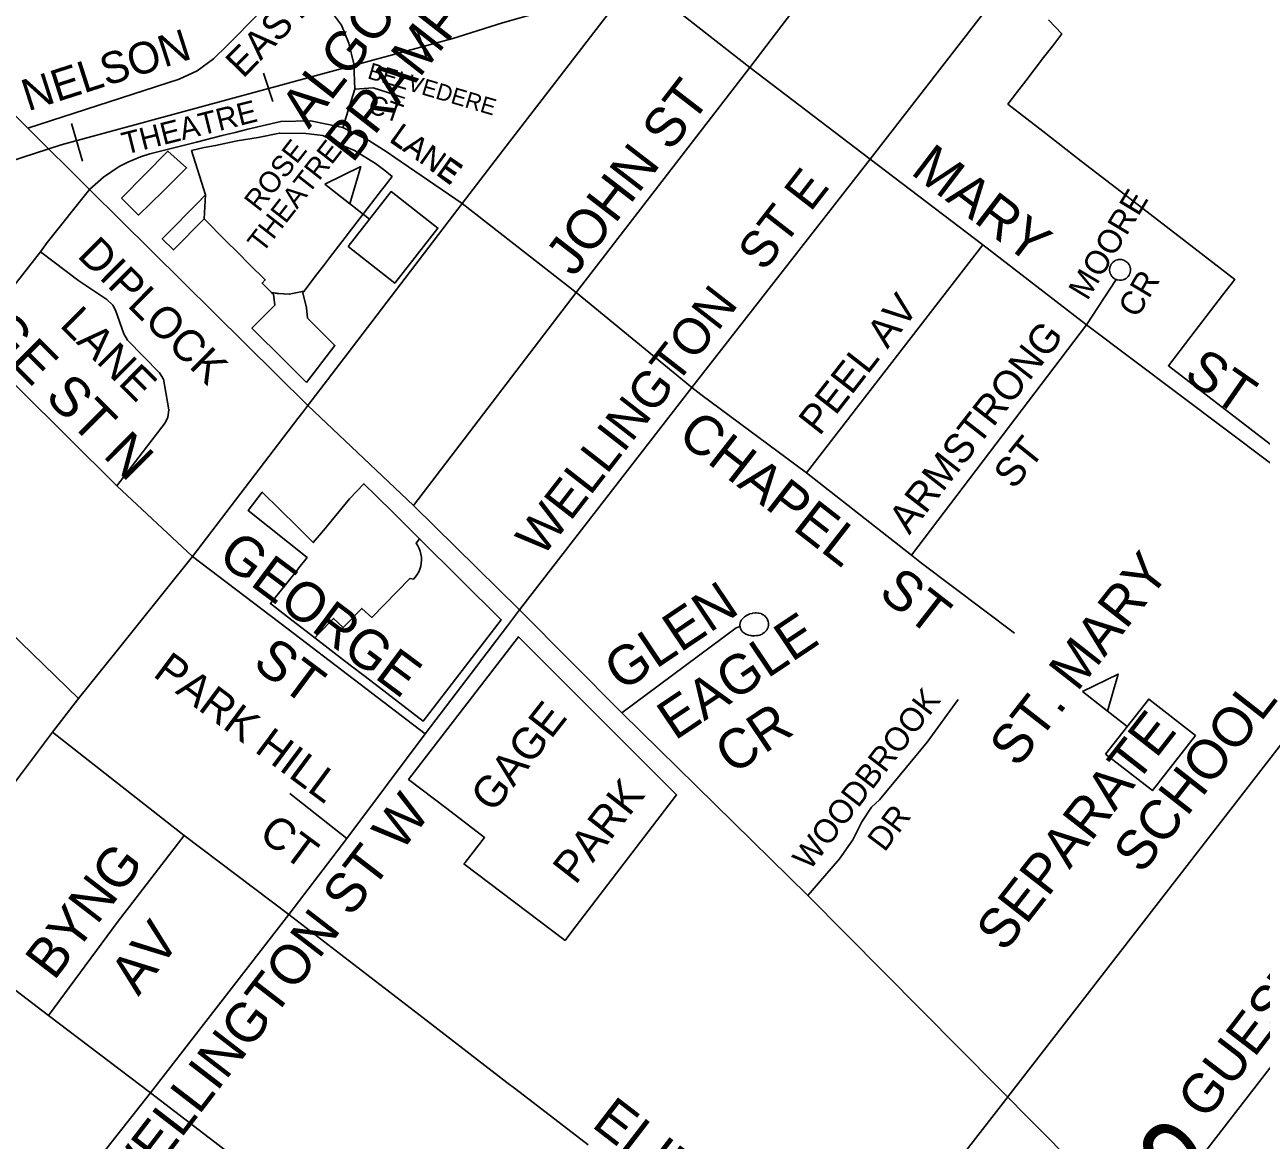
# Model space of a CAD drawing. Extents: x 586326 to 623965, y 4819854 to 4857850.
# Drawn here: x 599765 to 600548, y 4837268 to 4837975 of the extents above; entities that cross this region are included whole.
import ezdxf

# ---------------------------------------------------------------- set-up
doc = ezdxf.new("R2010")
doc.units = 0
for name, color, linetype in [('Lots_Concessions', 7, 'Continuous'), ('Major Rds and Hwys', 7, 'Continuous'), ('Major Rds Lbls', 7, 'Continuous'), ('Minor Rd Lbls', 7, 'Continuous'), ('Minor Rds', 7, 'Continuous'), ('Park Lbls', 7, 'Continuous'), ('Park Outlines', 7, 'Continuous'), ('Private Rd Lbls', 7, 'Continuous'), ('Private Rds', 7, 'Continuous'), ('Proposed Secondary Rds', 7, 'Continuous'), ('Pts of Interest', 7, 'Continuous'), ('Railways_lbls', 7, 'Continuous'), ('School Syms_Lbls', 7, 'Continuous'), ('Secondary Rds Lbls', 7, 'Continuous')]:
    doc.layers.add(name, color=color, linetype=linetype)

msp = doc.modelspace()

# ---------------------------------------------------------------- linework, layer by layer
at = {"layer": 'Lots_Concessions'}
for p, q in [((600387.79, 4837295.98), (600638.9, 4837619.9)), ((600308.22, 4837193.39), (600387.96, 4837296.17))]:
    msp.add_line(p, q, dxfattribs=at)
at = {"layer": 'Major Rds and Hwys'}
for points in [[(600069.85, 4837898.16), (600151.75, 4838004.72)], [(599766.6, 4837909.61), (599693.66, 4837982.93)], [(599805.77, 4837870.74), (599766.6, 4837909.61)], [(600042.05, 4837861.99), (600069.85, 4837898.16)], [(599944.17, 4837733.92), (599805.77, 4837870.74)], [(599944.17, 4837733.92), (599966.9, 4837763.68), (600042.05, 4837861.99)], [(599944.17, 4837733.92), (599941.01, 4837729.79), (599937.86, 4837725.67), (599871.13, 4837638.37)], [(599944.17, 4837733.92), (600011.24, 4837670.53)], [(600011.24, 4837670.53), (600078.31, 4837604.38)], [(599871.13, 4837638.37), (599835.07, 4837593.4), (599820.8, 4837575.6), (599818.11, 4837572.24), (599798.91, 4837548.29)], [(600078.31, 4837604.38), (600143.08, 4837539.15)], [(599798.91, 4837548.29), (599782.24, 4837526.96)], [(600143.08, 4837539.15), (600261.14, 4837423.38)], [(599782.24, 4837526.96), (599727.66, 4837454.38)], [(600261.14, 4837423.38), (600453.75, 4837229.28)]]:
    msp.add_lwpolyline(points, dxfattribs=at)
at = {"layer": 'Minor Rds'}
for points in [[(599766.6, 4837909.61), (599862.72, 4837940.59), (599873.96, 4837945.89), (599884.48, 4837953.64), (599893.1, 4837961.93), (599933.45, 4838002.96)], [(599933.45, 4838002.96), (599942.46, 4837997.39), (599948.24, 4837993.47), (599953.94, 4837988.08), (599959.77, 4837982.59), (599965.59, 4837974.93), (599970.08, 4837963.45), (599973.41, 4837950.48), (599973.91, 4837934.34)], [(600300.61, 4837889.91), (600378.98, 4837991.06), (600381.64, 4837994.46), (600383.31, 4837997.87)], [(600161.59, 4837982.44), (600169.54, 4837986.3), (600172.9, 4837986.96), (600176.85, 4837985.33), (600224.28, 4837948.01)], [(600114.14, 4837805.59), (600224.28, 4837948.01)], [(599973.91, 4837934.34), (599966.25, 4837910.05)], [(599873.65, 4837900.85), (599889.92, 4837904.95), (599898.06, 4837907), (599906.19, 4837909.05), (599926.99, 4837913.87), (599945.96, 4837914.37), (599956.11, 4837912.21), (599966.25, 4837910.05)], [(599966.25, 4837910.05), (599982.73, 4837901.73), (599994.37, 4837894.41), (599999.41, 4837890.98), (600042.05, 4837861.99)], [(599805.77, 4837870.74), (599814.62, 4837878.59), (599824.61, 4837885.33), (599830.03, 4837888.04), (599838.1, 4837891.49), (599844.12, 4837893.4), (599873.65, 4837900.85)], [(600300.61, 4837889.91), (600371.9, 4837835.63)], [(599805.77, 4837870.74), (599778.96, 4837837.28), (599774.72, 4837831.34)], [(600042.05, 4837861.99), (600114.14, 4837805.59)], [(600260.22, 4837691.2), (600371.9, 4837835.63)], [(600371.9, 4837835.63), (600437.76, 4837785.07)], [(599774.72, 4837831.34), (599730.31, 4837774.94)], [(599774.72, 4837831.34), (599799.02, 4837813.02), (599816.81, 4837801.09), (599820.59, 4837797.59), (599822.28, 4837794.35), (599827.63, 4837779.43), (599829.79, 4837775.43), (599850.23, 4837754.68), (599852.76, 4837750.72), (599856.09, 4837731.11), (599855.51, 4837726.57), (599853.66, 4837722.93), (599823.05, 4837682.97)], [(600456.43, 4837813.76), (600455.52, 4837814.22), (600455.31, 4837814.34), (600455.11, 4837814.47), (600454.92, 4837814.62), (600454.26, 4837815.2), (600454.08, 4837815.36), (600453.92, 4837815.54), (600453.77, 4837815.73), (600453.26, 4837816.45), (600453.13, 4837816.65), (600453.02, 4837816.86), (600452.92, 4837817.08), (600452.6, 4837817.9), (600452.52, 4837818.13), (600452.46, 4837818.36), (600452.42, 4837818.6), (600452.3, 4837819.47), (600452.28, 4837819.71), (600452.27, 4837819.95), (600452.29, 4837820.19), (600452.38, 4837821.06), (600452.42, 4837821.29), (600452.47, 4837821.52), (600452.53, 4837821.74), (600452.62, 4837821.95), (600453.04, 4837822.9), (600453.13, 4837823.08), (600453.23, 4837823.26), (600453.34, 4837823.44), (600453.47, 4837823.6), (600454.13, 4837824.39), (600454.27, 4837824.55), (600454.41, 4837824.69), (600454.57, 4837824.83), (600454.74, 4837824.95), (600455.59, 4837825.54), (600455.76, 4837825.65), (600455.94, 4837825.75), (600456.13, 4837825.83), (600456.32, 4837825.91), (600457.3, 4837826.24), (600457.5, 4837826.3), (600457.7, 4837826.35), (600457.9, 4837826.38), (600458.11, 4837826.4), (600459.14, 4837826.45), (600459.4, 4837826.45), (600459.65, 4837826.43), (600459.91, 4837826.39), (600461.41, 4837825.92)], [(600461.41, 4837825.92), (600461.93, 4837825.69), (600462.66, 4837825.27), (600462.86, 4837825.14), (600463.05, 4837824.99), (600463.23, 4837824.84), (600463.84, 4837824.26), (600464, 4837824.08), (600464.16, 4837823.9), (600464.29, 4837823.7), (600464.75, 4837822.99), (600464.87, 4837822.79), (600464.97, 4837822.57), (600465.06, 4837822.35), (600465.33, 4837821.55), (600465.4, 4837821.33), (600465.45, 4837821.09), (600465.48, 4837820.86), (600465.56, 4837820.02), (600465.57, 4837819.78), (600465.56, 4837819.54), (600465.54, 4837819.3), (600465.41, 4837818.47), (600465.37, 4837818.24), (600465.31, 4837818.01), (600465.23, 4837817.78), (600464.91, 4837817), (600464.81, 4837816.78), (600464.7, 4837816.58), (600464.56, 4837816.38), (600464.07, 4837815.69), (600463.93, 4837815.51), (600463.76, 4837815.33), (600463.59, 4837815.17), (600462.95, 4837814.62), (600462.76, 4837814.47), (600462.56, 4837814.34), (600462.36, 4837814.22), (600461.6, 4837813.84), (600461.41, 4837813.75), (600461.2, 4837813.67), (600460.99, 4837813.61), (600460.14, 4837813.39), (600459.91, 4837813.34), (600459.67, 4837813.31), (600459.43, 4837813.3), (600458.55, 4837813.29), (600457.12, 4837813.45), (600456.43, 4837813.76)], [(600437.76, 4837785.07), (600456.43, 4837813.76)], [(600011.24, 4837670.53), (600114.14, 4837805.59)], [(600114.14, 4837805.59), (600187.64, 4837745.41)], [(600326.78, 4837639.03), (600437.76, 4837785.07)], [(600437.76, 4837785.07), (600612.99, 4837653.35)], [(599823.05, 4837682.97), (599730.31, 4837774.94)], [(600187.64, 4837745.41), (600193.16, 4837740.89), (600260.22, 4837691.2)], [(600260.22, 4837691.2), (600326.78, 4837639.03)], [(599798.91, 4837548.29), (599659.24, 4837683.67)], [(599871.13, 4837638.37), (599823.05, 4837682.97)], [(599871.13, 4837638.37), (599931.69, 4837592.14), (600018.59, 4837525.82)], [(600326.78, 4837639.03), (600333.04, 4837634.06), (600392.12, 4837589.69)], [(600218.09, 4837593.88), (600218.01, 4837594.36), (600217.98, 4837594.79), (600217.99, 4837595.01), (600218.02, 4837595.23), (600218.16, 4837596.11), (600218.2, 4837596.32), (600218.25, 4837596.53), (600218.33, 4837596.74), (600218.41, 4837596.93), (600218.79, 4837597.74), (600218.89, 4837597.93), (600219.01, 4837598.11), (600219.13, 4837598.29), (600219.27, 4837598.45), (600219.42, 4837598.61), (600220.49, 4837599.64), (600220.68, 4837599.81), (600220.88, 4837599.96), (600222.11, 4837600.8), (600222.32, 4837600.94), (600222.54, 4837601.05), (600223.89, 4837601.68), (600224.12, 4837601.77), (600224.36, 4837601.85), (600225.8, 4837602.24), (600226.04, 4837602.3), (600226.29, 4837602.34), (600227.77, 4837602.49), (600228.02, 4837602.5), (600228.27, 4837602.5), (600229.76, 4837602.4), (600230.01, 4837602.37), (600230.26, 4837602.32), (600231.25, 4837602.09), (600231.49, 4837602.02), (600231.73, 4837601.93), (600231.96, 4837601.82), (600232.86, 4837601.34), (600233.08, 4837601.21), (600233.28, 4837601.07), (600233.48, 4837600.9), (600234.23, 4837600.22), (600234.41, 4837600.04), (600234.57, 4837599.84), (600234.72, 4837599.64), (600235.27, 4837598.78), (600235.4, 4837598.57), (600235.51, 4837598.34), (600235.6, 4837598.1), (600235.92, 4837597.14), (600235.99, 4837596.89), (600236.04, 4837596.64), (600236.07, 4837596.39), (600236.14, 4837595.38), (600236.14, 4837595.12), (600236.13, 4837594.87), (600236.09, 4837594.62), (600235.91, 4837593.62), (600235.85, 4837593.36), (600235.76, 4837593.12), (600235.66, 4837592.87), (600235.54, 4837592.64), (600234.98, 4837591.71), (600234.88, 4837591.54), (600234.75, 4837591.38), (600234.62, 4837591.22), (600233.89, 4837590.42), (600233.75, 4837590.28), (600233.6, 4837590.14), (600233.44, 4837590.02), (600232.57, 4837589.38), (600232.4, 4837589.27), (600232.22, 4837589.16), (600232.04, 4837589.07), (600231.05, 4837588.63), (600230.87, 4837588.55), (600230.67, 4837588.48), (600230.48, 4837588.43), (600229.42, 4837588.19), (600229.17, 4837588.15), (600228.92, 4837588.12), (600228.66, 4837588.12), (600228.45, 4837588.13), (600227.23, 4837588.01), (600226.75, 4837588)], [(600143.08, 4837539.15), (600215.54, 4837593.01), (600218.09, 4837593.88)], [(600226.75, 4837588), (600225.33, 4837588.09), (600225.09, 4837588.11), (600224.86, 4837588.16), (600223.47, 4837588.47), (600223.24, 4837588.53), (600223.02, 4837588.61), (600221.69, 4837589.14), (600221.52, 4837589.21), (600221.36, 4837589.3), (600221.2, 4837589.39), (600220.45, 4837589.87), (600220.27, 4837589.99), (600220.1, 4837590.13), (600219.94, 4837590.27), (600219.79, 4837590.43), (600219.21, 4837591.11), (600219.07, 4837591.27), (600218.95, 4837591.45), (600218.84, 4837591.64), (600218.74, 4837591.83), (600218.36, 4837592.72), (600218.09, 4837593.88)], [(599782.24, 4837526.96), (599865.7, 4837461.44)], [(599932.78, 4837488.02), (599968.97, 4837459.67)], [(599865.7, 4837461.44), (599823.3, 4837406.37), (599779.82, 4837347.46)], [(599865.7, 4837461.44), (599932.22, 4837411.44)], [(600473.51, 4837210.46), (600639.8, 4837425.2)], [(599694.77, 4837412.28), (599779.82, 4837347.46)], [(599932.22, 4837411.44), (600017.2, 4837345.93), (600070.26, 4837305.02), (600075.9, 4837300.86), (600121.87, 4837265.5)], [(599779.82, 4837347.46), (599844.48, 4837298.43)], [(599844.48, 4837298.43), (600036.69, 4837150.98)]]:
    msp.add_lwpolyline(points, dxfattribs=at)
at = {"layer": 'Park Outlines'}
msp.add_lwpolyline([(600413.62, 4837978.23), (600422.08, 4837969.31), (600416.3, 4837961.81), (600410.53, 4837954.31), (600399.19, 4837939.59), (600393.39, 4837932.07), (600387.86, 4837924.88), (600399.87, 4837915.51), (600409.98, 4837907.67), (600434.38, 4837888.78), (600459.63, 4837869.33), (600465.18, 4837865.06), (600500.98, 4837837.48), (600531.69, 4837813.83), (600523.95, 4837803.78), (600503.85, 4837777.66), (600489.56, 4837759.1), (600579.88, 4837689.6)], dxfattribs=at)
for points in [[(599942.85, 4837906.27), (599926.18, 4837906.56), (599912.63, 4837903.76), (599899.43, 4837901.54), (599885.71, 4837898.66), (599878.54, 4837897.33), (599870.45, 4837895.39), (599879.29, 4837867.36), (599878.39, 4837852.12), (599892.25, 4837838.33), (599899.77, 4837830.84), (599907.06, 4837823.58), (599917.21, 4837813.49), (599915.18, 4837811.48), (599921.23, 4837805.43), (599925.72, 4837804.85), (599932.35, 4837804.4), (599940.74, 4837806.24), (599941.64, 4837806.15), (599950.12, 4837817.27), (599954.01, 4837822.35), (599957.91, 4837827.42), (599965.7, 4837837.57), (599977.6, 4837853.06), (599990.96, 4837870.45), (599992.46, 4837872.41), (599997.52, 4837878.93), (599993.05, 4837882.73), (599986.95, 4837887.19), (599973.83, 4837895.4), (599965.61, 4837898.89), (599953.63, 4837905.05)], [(599826.16, 4837865.23), (599829.11, 4837862.29), (599836.9, 4837854.53), (599852.37, 4837869.72), (599867.35, 4837884.43), (599861.35, 4837889.75), (599855.35, 4837895.07)], [(599879.29, 4837867.36), (599876.8, 4837864.84), (599876.72, 4837864.76), (599851.93, 4837839.56), (599859.05, 4837832.47), (599878.39, 4837852.12)], [(599943.35, 4837748.48), (599958.6, 4837768.33), (599961.36, 4837771.91), (599943.96, 4837789.26), (599943.25, 4837795.84), (599940.74, 4837806.24), (599932.35, 4837804.4), (599928.73, 4837804.64), (599925.72, 4837804.85), (599924.69, 4837804.93), (599921.23, 4837805.43), (599922.4, 4837804.46), (599923.16, 4837797.43), (599908.71, 4837782.99), (599910.87, 4837780.84), (599916.33, 4837775.41), (599922.17, 4837769.59), (599925.18, 4837766.58), (599936.97, 4837754.85)], [(599948.6, 4837586.73), (599950.62, 4837589.05), (599960.47, 4837599.07), (599966.56, 4837593.29), (599978.38, 4837605.36), (599984.74, 4837599.67), (600008.87, 4837624.36), (600011.11, 4837623.9), (600012.38, 4837625.32), (600013.49, 4837626.87), (600014.42, 4837628.54), (600015.17, 4837630.3), (600015.72, 4837632.13), (600016.06, 4837634), (600016.2, 4837635.91), (600016.12, 4837637.82), (600015.84, 4837639.7), (600015.35, 4837641.55), (600014.67, 4837643.33), (600013.79, 4837645.03), (600012.73, 4837646.61), (600014.96, 4837649.47), (600000.94, 4837663.34), (599984.95, 4837679.16), (599982.29, 4837681.79), (599979.69, 4837684.36), (599970.48, 4837674.83), (599954.17, 4837654.64), (599947.57, 4837647.09), (599937.6, 4837656.96), (599915.25, 4837679.09), (599906.27, 4837667.47), (599943.69, 4837637.62), (599938.5, 4837631.08), (599937.55, 4837629.88), (599920.49, 4837608.41), (599923.39, 4837606.18), (599931.35, 4837600.04)], [(600014.96, 4837649.47), (600012.73, 4837646.61), (600013.79, 4837645.03), (600014.67, 4837643.33), (600015.35, 4837641.55), (600015.84, 4837639.7), (600016.12, 4837637.82), (600016.2, 4837635.91), (600016.06, 4837634), (600015.72, 4837632.13), (600015.17, 4837630.3), (600014.42, 4837628.54), (600013.49, 4837626.87), (600012.38, 4837625.32), (600011.11, 4837623.9), (600008.87, 4837624.36), (599984.74, 4837599.67), (599978.38, 4837605.36), (599966.56, 4837593.29), (599960.47, 4837599.07), (599950.62, 4837589.05), (599948.6, 4837586.73), (599967.42, 4837572.22), (599984.01, 4837559.43), (600017.18, 4837533.84), (600066.8, 4837598.18)], [(600043.81, 4837444.4), (600043.05, 4837443.45), (600107.2, 4837395.06), (600111.46, 4837400.61), (600177.87, 4837487.23), (600077.72, 4837587.38), (600008.01, 4837497), (600032.17, 4837478.51), (600056.17, 4837460.14)]]:
    msp.add_lwpolyline(points, close=True, dxfattribs=at)
at = {"layer": 'Private Rds'}
for points in [[(599973.91, 4837934.34), (599985.66, 4837935.3), (599994.27, 4837932.41), (600005.73, 4837928.56)], [(600261.14, 4837423.38), (600271.81, 4837435.89), (600281.1, 4837446.78), (600289.68, 4837458.67), (600295.23, 4837470.23), (600301.36, 4837479.35), (600306.44, 4837484.16), (600336.64, 4837520.68), (600356.39, 4837547.66)]]:
    msp.add_lwpolyline(points, dxfattribs=at)
at = {"layer": 'Proposed Secondary Rds'}
for points in [[(600224.28, 4837948.01), (600311.47, 4838062.86)], [(600224.28, 4837948.01), (600300.61, 4837889.91)], [(600187.64, 4837745.41), (600300.61, 4837889.91)], [(600078.31, 4837604.38), (600187.64, 4837745.41)], [(600078.31, 4837604.38), (600070.68, 4837594.34), (600018.59, 4837525.82)], [(600018.59, 4837525.82), (599968.97, 4837459.67)], [(599968.97, 4837459.67), (599932.22, 4837411.44)], [(599932.22, 4837411.44), (599844.48, 4837298.43)], [(599844.48, 4837298.43), (599774.92, 4837210.43)]]:
    msp.add_lwpolyline(points, dxfattribs=at)
at = {"layer": 'Railways_lbls'}
for p, q in [((600013.57, 4837971.34), (600019.57, 4837953.34)), ((599915.99, 4837944.47), (599921.99, 4837926.47)), ((599794.35, 4837912.63), (599801.35, 4837888.63))]:
    msp.add_line(p, q, dxfattribs=at)
for points in [[(600569.96, 4838123.8), (600536.58, 4838113.01), (600107.93, 4837987.81), (600067.45, 4837976.32), (600036, 4837966.54), (600019.69, 4837961.95)], [(600019.69, 4837961.95), (599787.85, 4837899.03), (599622.39, 4837845.35), (599599.62, 4837838.63)]]:
    msp.add_lwpolyline(points, dxfattribs=at)
at = {"layer": 'School Syms_Lbls'}
for p, q in [((599983.32, 4837852.03), (599954.91, 4837874.23)), ((600463.46, 4837530.53), (600435.05, 4837552.73))]:
    msp.add_line(p, q, dxfattribs=at)
for points in [[(599954.91, 4837874.23), (599977.69, 4837885.26), (599970.77, 4837861.76)], [(599969.69, 4837834.59), (599996.95, 4837869.48), (600026.56, 4837846.35), (599999.29, 4837811.45)], [(600435.05, 4837552.73), (600457.83, 4837563.76), (600450.91, 4837540.26)], [(600449.82, 4837513.09), (600477.09, 4837547.98), (600506.7, 4837524.85), (600479.43, 4837489.95)]]:
    msp.add_lwpolyline(points, close=True, dxfattribs=at)

# ---------------------------------------------------------------- texts
at = {"layer": 'Major Rds Lbls'}
msp.add_text('MAIN    ST   S', height=49.998, rotation=135.23343, dxfattribs=at).set_placement((600788.31, 4836985.66))
at = {"layer": 'Minor Rd Lbls'}
for s, height, rotation, p in [('EAST', 17.715, 45.64567, (599903.14, 4837940.71)), ('NELSON', 19.998, 17.79601, (599766.8, 4837920.27)), ('JOHN ST', 25.002, 52.40783, (600112.77, 4837814.69)), ('THEATRE', 14, 14.07454, (599828.36, 4837892.84)), ('LANE', 14, 323.44225, (599995.46, 4837902.3)), ('LANE', 14, 325.78415, (599995.17, 4837901.35)), ('MARY', 25.002, 322.713, (600325.48, 4837881.1)), ('MOORE', 15, 58.9402, (600438.25, 4837799.83)), ('GEORGE ST N', 25.002, 315.00002, (599666.48, 4837849.03)), ('DIPLOCK ', 19.998, 315.30317, (599797.43, 4837828.37)), ('CR', 15, 59.19903, (600469.82, 4837788.69)), ('PEEL AV', 18.456, 52.00002, (600268.42, 4837714.12)), ('LANE', 19.998, 315.30317, (599786.29, 4837784.29)), ('ARMSTRONG', 18.456, 52.05422, (600325.38, 4837651.55)), ('ST', 24.996, 325.3102, (600498.43, 4837751.11)), ('CHAPEL   ST', 25.002, 322.08691, (600177.43, 4837712.84)), ('ST', 18.456, 51.2277, (600391.76, 4837680.13)), ('GEORGE', 25.002, 323.25946, (599886.03, 4837636.11)), ('GLEN', 25.002, 33.87083, (600143.18, 4837552.25)), ('EAGLE', 25.002, 33.87083, (600176.86, 4837521.32)), ('ST', 25.002, 323.25946, (599908.25, 4837568.73)), ('PARK HILL', 19.998, 323.36591, (599845.3, 4837562.82)), ('CR', 25.002, 33.87083, (600213.38, 4837499.5)), ('CT', 19.998, 323.36591, (599912.16, 4837460.36)), ('BYNG', 25.002, 52.48091, (599783.26, 4837368.96)), ('GUEST ST', 25.002, 52.50198, (600513.48, 4837280.48)), ('AV', 25.002, 52.48091, (599836.76, 4837359.14)), ('ELIZABETH', 25.002, 322.34432, (600123.3, 4837277.44))]:
    msp.add_text(s, height=height, rotation=rotation, dxfattribs=at).set_placement(p)
at = {"layer": 'Park Lbls'}
for s, p in [('GAGE', (600061.65, 4837475.21)), ('PARK', (600113.76, 4837429.68))]:
    msp.add_text(s, height=19.992, rotation=52.00002, dxfattribs=at).set_placement(p)
at = {"layer": 'Private Rd Lbls'}
for s, height, rotation, p in [('BELVEDERE', 10.418, 343.48373, (599981.44, 4837941.33)), ('CT', 12, 340.68925, (599981.44, 4837919.85)), ('WOODBROOK', 15, 52.30995, (600262.2, 4837438.74)), ('DR', 15, 52.94349, (600309.69, 4837450.49))]:
    msp.add_text(s, height=height, rotation=rotation, dxfattribs=at).set_placement(p)
at = {"layer": 'Pts of Interest'}
for s, p in [('ROSE', (599913.29, 4837855.98)), ('THEATRE', (599915.4, 4837829.89))]:
    msp.add_text(s, height=13.293, rotation=52.00002, dxfattribs=at).set_placement(p)
at = {"layer": 'School Syms_Lbls'}
for s, p in [('ALGOMA UNIVERSITY', (599944.78, 4837908.55)), ('BRAMPTON CAMPUS', (599972.52, 4837886.88)), ('ST. MARY', (600394.07, 4837503.69)), ('SCHOOL', (600472.66, 4837436.36)), ('SEPARATE', (600385.68, 4837386.85))]:
    msp.add_text(s, height=25, rotation=52.00002, dxfattribs=at).set_placement(p)
at = {"layer": 'Secondary Rds Lbls'}
for s, height, rotation, p in [('WELLINGTON   ST E', 23.0267, 52.15925, (600092.69, 4837637.14)), ('WELLINGTON ST W', 25.002, 52.40783, (599830.96, 4837226.6))]:
    msp.add_text(s, height=height, rotation=rotation, dxfattribs=at).set_placement(p)

doc.saveas('drawing.dxf')
